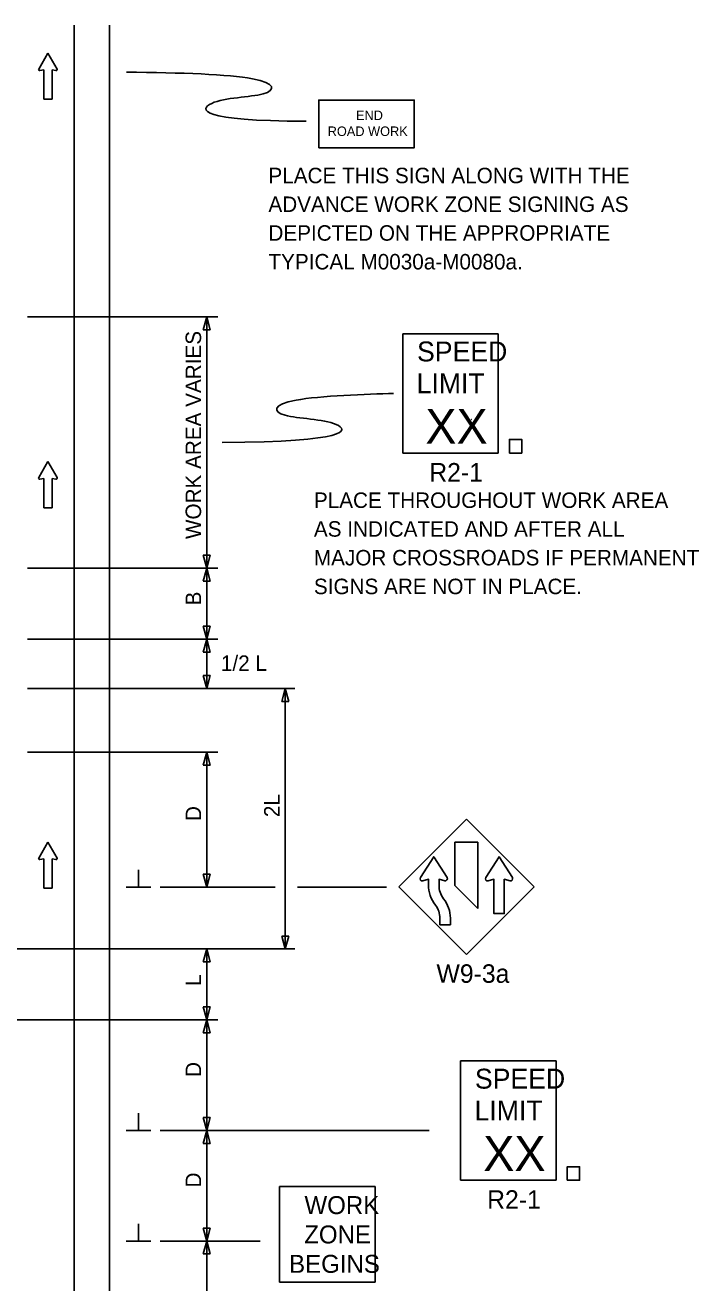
# Model space of a CAD drawing. Extents: x 16737 to 18482, y 6986 to 8195.
# Drawn here: x 17076 to 17381, y 7597 to 8166 of the extents above; entities that cross this region are included whole.
import ezdxf

# ---------------------------------------------------------------- set-up
doc = ezdxf.new("R2010")
doc.units = 0
for name, color, linetype in [('MT_SCRATCH_LEVEL_E', 7, 'Continuous'), ('PAVT_EDGE_EX', 7, 'Continuous'), ('TRAFFIC_SIGNS_PR', 7, 'Continuous'), ('TYPICAL_TEXT_DIMEN_PR', 7, 'Continuous')]:
    doc.layers.add(name, color=color, linetype=linetype)

msp = doc.modelspace()

# ---------------------------------------------------------------- linework, layer by layer
at = {"layer": 'MT_SCRATCH_LEVEL_E'}
for p, q in [((17086.43, 8153.59), (17082.31, 8146.35)), ((17090.57, 8146.35), (17086.43, 8153.59)), ((17082.8, 8145.66), (17084.57, 8145.98)), ((17084.57, 8145.98), (17084.57, 8132.72)), ((17088.32, 8132.72), (17088.32, 8145.98)), ((17088.32, 8145.98), (17090.09, 8145.66)), ((17084.57, 8132.72), (17088.32, 8132.72)), ((17086.43, 7968.78), (17082.32, 7961.54)), ((17086.43, 7968.78), (17082.32, 7961.54)), ((17090.57, 7961.54), (17086.43, 7968.78)), ((17090.57, 7961.54), (17086.43, 7968.78)), ((17082.8, 7960.86), (17084.58, 7961.17)), ((17082.8, 7960.86), (17084.58, 7961.17)), ((17084.58, 7961.17), (17084.58, 7947.91)), ((17084.58, 7961.17), (17084.58, 7947.91)), ((17088.32, 7947.91), (17088.32, 7961.17)), ((17088.32, 7961.17), (17090.09, 7960.86)), ((17088.32, 7947.91), (17088.32, 7961.17)), ((17088.32, 7961.17), (17090.09, 7960.86)), ((17084.58, 7947.91), (17088.32, 7947.91)), ((17084.58, 7947.91), (17088.32, 7947.91)), ((17086.43, 7796.66), (17082.31, 7789.42)), ((17090.57, 7789.42), (17086.43, 7796.66)), ((17082.8, 7788.74), (17084.57, 7789.06)), ((17084.57, 7789.06), (17084.57, 7775.8)), ((17088.32, 7775.8), (17088.32, 7789.06)), ((17088.32, 7789.06), (17090.09, 7788.74)), ((17084.57, 7775.8), (17088.32, 7775.8))]:
    msp.add_line(p, q, dxfattribs=at)
for centre, start, end in [((17082.72, 8146.12), 150.4248, 279.9638), ((17090.16, 8146.12), 260.0362, 29.7731), ((17082.72, 7961.32), 150.4248, 279.9638), ((17082.72, 7961.32), 150.4248, 279.9638), ((17090.16, 7961.32), 260.0362, 29.7731), ((17090.16, 7961.32), 260.0362, 29.7731), ((17082.72, 7789.2), 150.4248, 279.9638), ((17090.16, 7789.2), 260.0362, 29.7731)]:
    msp.add_arc(centre, 0.463, start, end, dxfattribs=at)
at = {"layer": 'PAVT_EDGE_EX'}
for p, q in [((17098.25, 8166.21), (17098.25, 7372.95)), ((17114.25, 8166.21), (17114.25, 7372.95))]:
    msp.add_line(p, q, dxfattribs=at)
at = {"layer": 'TRAFFIC_SIGNS_PR'}
for p, q in [((17246.82, 8026.64), (17290.02, 8026.64)), ((17246.82, 7972.64), (17246.82, 8026.64)), ((17290.02, 7972.64), (17290.02, 8026.64)), ((17246.82, 7972.64), (17290.02, 7972.64)), ((17275.67, 7806.98), (17245.12, 7776.43)), ((17306.21, 7776.43), (17275.67, 7806.98)), ((17270.37, 7796.61), (17270.37, 7777.03)), ((17280.72, 7796.61), (17270.37, 7796.61)), ((17280.72, 7766.67), (17280.72, 7796.61)), ((17270.37, 7777.03), (17280.72, 7766.67)), ((17245.12, 7776.43), (17275.67, 7745.89)), ((17275.67, 7745.89), (17306.21, 7776.43)), ((17272.99, 7697.69), (17316.19, 7697.69)), ((17272.99, 7643.69), (17272.99, 7697.69)), ((17316.19, 7643.69), (17316.19, 7697.69)), ((17191.19, 7597.63), (17191.19, 7640.83)), ((17191.19, 7640.83), (17234.39, 7640.83)), ((17234.39, 7597.63), (17234.39, 7640.83)), ((17272.99, 7643.69), (17316.19, 7643.69)), ((17191.19, 7597.63), (17234.39, 7597.63))]:
    msp.add_line(p, q, dxfattribs=at)
for points in [[(17208.85, 8110.74), (17252.06, 8110.74), (17252.06, 8132.34), (17208.85, 8132.34)], [(17295.03, 7972.64), (17300.63, 7972.64), (17300.63, 7978.81), (17295.03, 7978.81)], [(17321.21, 7643.69), (17326.8, 7643.69), (17326.8, 7649.86), (17321.21, 7649.86)]]:
    msp.add_lwpolyline(points, close=True, dxfattribs=at)
for points in [[(17266.88, 7780.6), (17260.89, 7790.02), (17254.9, 7780.6)], [(17296.39, 7780.6), (17290.4, 7790.02), (17284.4, 7780.6)], [(17255.95, 7779.18), (17258.53, 7779.89), (17258.52, 7777.38)], [(17263.24, 7777.27), (17263.25, 7779.89), (17265.83, 7779.18)], [(17285.45, 7779.18), (17288.04, 7779.89), (17288.04, 7764.37), (17292.76, 7764.37), (17292.76, 7779.89), (17295.34, 7779.18)], [(17263.66, 7762.25), (17263.66, 7759.27), (17268.38, 7759.27), (17268.38, 7762.25)]]:
    msp.add_lwpolyline(points, dxfattribs=at)
for centre, radius, start, end in [((17255.69, 7780.09), 0.945, 147.5204, 285.3986), ((17272.69, 7776.97), 14.17, 178.3293, 218.5427), ((17251.44, 7777.64), 11.81, 358.1894, 0.0048), ((17272.69, 7776.97), 9.45, 178.1936, 218.5465), ((17266.08, 7780.1), 0.947, 254.6828, 32.2708), ((17262.71, 7767.79), 11.81, 74.68, 74.6808), ((17276.85, 7786.94), 11.81, 212.4569, 212.4665), ((17285.2, 7780.09), 0.946, 147.5497, 285.3316), ((17295.59, 7780.09), 0.943, 254.6778, 32.4665), ((17306.35, 7786.94), 11.81, 212.4569, 212.4665), ((17254.21, 7762.25), 9.45, 0, 38.5457), ((17254.21, 7762.25), 14.17, 0, 38.5422)]:
    msp.add_arc(centre, radius, start, end, dxfattribs=at)
at = {"layer": 'TYPICAL_TEXT_DIMEN_PR'}
for p, q in [((17077.19, 8034.26), (17163.25, 8034.26)), ((17156.68, 8028.4), (17158.25, 8034.26)), ((17158.25, 8034.26), (17158.25, 7920.53)), ((17158.25, 8034.26), (17159.82, 8028.4)), ((17158.25, 8028.4), (17156.68, 8028.4)), ((17159.82, 8028.4), (17158.25, 8028.4)), ((17158.25, 7920.53), (17156.68, 7926.4)), ((17156.68, 7926.4), (17158.25, 7926.4)), ((17158.25, 7926.4), (17159.82, 7926.4)), ((17159.82, 7926.4), (17158.25, 7920.53)), ((17077.19, 7920.53), (17163.25, 7920.53)), ((17156.68, 7914.67), (17158.25, 7920.53)), ((17158.25, 7920.53), (17158.25, 7888.46)), ((17158.25, 7920.53), (17159.82, 7914.67)), ((17158.25, 7914.67), (17156.68, 7914.67)), ((17159.82, 7914.67), (17158.25, 7914.67)), ((17158.25, 7888.46), (17156.68, 7894.32)), ((17156.68, 7894.32), (17158.25, 7894.32)), ((17158.25, 7895.55), (17158.25, 7891.96)), ((17158.25, 7894.32), (17159.82, 7894.32)), ((17159.82, 7894.32), (17158.25, 7888.46)), ((17077.19, 7888.46), (17163.25, 7888.46)), ((17156.68, 7882.6), (17158.25, 7888.46)), ((17158.25, 7888.46), (17158.25, 7866.21)), ((17158.25, 7888.46), (17159.82, 7882.6)), ((17158.25, 7882.6), (17156.68, 7882.6)), ((17159.82, 7882.6), (17158.25, 7882.6)), ((17158.25, 7866.21), (17156.68, 7872.07)), ((17156.68, 7872.07), (17158.25, 7872.07)), ((17158.25, 7872.07), (17159.82, 7872.07)), ((17159.82, 7872.07), (17158.25, 7866.21)), ((17077.19, 7866.21), (17198.06, 7866.21)), ((17192.16, 7860.35), (17193.73, 7866.21)), ((17193.73, 7866.21), (17195.3, 7860.35)), ((17193.73, 7866.21), (17193.73, 7748.33)), ((17193.73, 7860.35), (17192.16, 7860.35)), ((17195.3, 7860.35), (17193.73, 7860.35)), ((17077.19, 7837.4), (17163.25, 7837.4)), ((17156.68, 7831.54), (17158.25, 7837.4)), ((17158.25, 7837.4), (17158.25, 7776.36)), ((17158.25, 7837.4), (17159.82, 7831.54)), ((17158.25, 7831.54), (17156.68, 7831.54)), ((17159.82, 7831.54), (17158.25, 7831.54)), ((17127.37, 7776.36), (17127.37, 7784.15)), ((17158.25, 7776.36), (17156.68, 7782.22)), ((17156.68, 7782.22), (17158.25, 7782.22)), ((17158.25, 7782.22), (17159.82, 7782.22)), ((17159.82, 7782.22), (17158.25, 7776.36)), ((17133, 7776.36), (17121.75, 7776.36)), ((17137.25, 7776.36), (17189.24, 7776.36)), ((17199.25, 7776.36), (17239.57, 7776.36)), ((17193.73, 7748.33), (17192.16, 7754.2)), ((17192.16, 7754.2), (17193.73, 7754.2)), ((17193.73, 7754.2), (17195.3, 7754.2)), ((17195.3, 7754.2), (17193.73, 7748.33)), ((17054, 7748.33), (17198.06, 7748.33)), ((17156.68, 7742.47), (17158.25, 7748.33)), ((17158.25, 7748.33), (17158.25, 7716.23)), ((17158.25, 7748.33), (17159.82, 7742.47)), ((17158.25, 7742.47), (17156.68, 7742.47)), ((17159.82, 7742.47), (17158.25, 7742.47)), ((17158.25, 7716.23), (17156.68, 7722.09)), ((17156.68, 7722.09), (17158.25, 7722.09)), ((17158.25, 7722.09), (17159.82, 7722.09)), ((17159.82, 7722.09), (17158.25, 7716.23)), ((17034.65, 7716.23), (17163.25, 7716.23)), ((17156.68, 7710.37), (17158.25, 7716.23)), ((17158.25, 7716.23), (17158.25, 7666.23)), ((17158.25, 7716.23), (17159.82, 7710.37)), ((17158.25, 7710.37), (17156.68, 7710.37)), ((17159.82, 7710.37), (17158.25, 7710.37)), ((17127.37, 7666.23), (17127.37, 7674.02)), ((17158.25, 7666.23), (17156.68, 7672.09)), ((17156.68, 7672.09), (17158.25, 7672.09)), ((17158.25, 7672.09), (17159.82, 7672.09)), ((17159.82, 7672.09), (17158.25, 7666.23)), ((17133, 7666.23), (17121.75, 7666.23)), ((17137.25, 7666.23), (17258.8, 7666.23)), ((17156.68, 7660.37), (17158.25, 7666.23)), ((17158.25, 7666.23), (17158.25, 7616.23)), ((17158.25, 7666.23), (17159.82, 7660.37)), ((17158.25, 7660.37), (17156.68, 7660.37)), ((17159.82, 7660.37), (17158.25, 7660.37)), ((17127.37, 7616.23), (17127.37, 7624.02)), ((17158.25, 7616.23), (17156.68, 7622.09)), ((17156.68, 7622.09), (17158.25, 7622.09)), ((17158.25, 7622.09), (17159.82, 7622.09)), ((17159.82, 7622.09), (17158.25, 7616.23)), ((17133, 7616.23), (17121.75, 7616.23)), ((17137.25, 7616.23), (17182.4, 7616.23)), ((17156.68, 7610.37), (17158.25, 7616.23)), ((17158.25, 7616.23), (17159.82, 7610.37)), ((17158.25, 7616.23), (17158.25, 7566.23)), ((17158.25, 7610.37), (17156.68, 7610.37)), ((17159.82, 7610.37), (17158.25, 7610.37))]:
    msp.add_line(p, q, dxfattribs=at)
for points, degree in [([(17203.12, 8122.78), (17154.66, 8122.78), (17154.66, 8133.54), (17189.57, 8133.54), (17189.57, 8143.2), (17146.71, 8144.72), (17121.92, 8144.98)], 3), ([(17165.27, 7977.42), (17222.82, 7977.8), (17222.39, 7988.15), (17187.91, 7988.15), (17187.91, 7997.81), (17230.77, 7999.33), (17242.68, 7999.59)], 3), ([(17277.82, 7987.86), (17277.84, 7987.86), (17277.85, 7987.86), (17277.85, 7987.86)], 2)]:
    msp.add_open_spline(points, degree=degree, dxfattribs=at)

# ---------------------------------------------------------------- texts
at = {"layer": 'TRAFFIC_SIGNS_PR'}
for s, height, p in [('END', 4.31, (17225.73, 8123.26)), ('ROAD WORK', 4.31, (17212.92, 8116.07)), ('PLACE THIS SIGN ALONG WITH THE', 7, (17186.12, 8094.71)), ('ADVANCE WORK ZONE SIGNING AS', 7, (17186.12, 8081.71)), ('DEPICTED ON THE APPROPRIATE', 7, (17186.12, 8068.71)), ('TYPICAL M0030a-M0080a.', 7, (17186.12, 8055.71)), ('SPEED', 9, (17253.31, 8014.11)), ('LIMIT', 9, (17253.12, 7999.71)), ('XX', 15.785, (17257.07, 7976.86)), ('R2-1', 8.37, (17258.83, 7959.77)), ('PLACE THROUGHOUT WORK AREA', 7, (17206.68, 7947.83)), ('AS INDICATED AND AFTER ALL', 7, (17206.68, 7934.83)), ('MAJOR CROSSROADS IF PERMANENT', 7, (17206.68, 7921.83)), ('SIGNS ARE NOT IN PLACE.', 7, (17206.68, 7908.83)), ('W9-3a', 8.37, (17262.1, 7733.02)), ('SPEED', 9, (17279.48, 7685.16)), ('LIMIT', 9, (17279.3, 7670.76)), ('XX', 15.785, (17283.24, 7647.92)), ('WORK', 8.119, (17202.44, 7628.41)), ('R2-1', 8.37, (17285, 7630.82)), ('ZONE', 8.119, (17202.31, 7615.13)), ('BEGINS', 8.119, (17195.48, 7601.84))]:
    msp.add_text(s, height=height, dxfattribs=at).set_placement(p)
at = {"layer": 'TYPICAL_TEXT_DIMEN_PR'}
for s, p in [('WORK AREA VARIES', (17155.69, 7933.75)), ('B', (17155.69, 7903.73)), ('2L', (17191.17, 7807.99)), ('D', (17155.69, 7806.21)), ('L', (17155.69, 7731.64)), ('D', (17155.69, 7690.45)), ('D', (17155.69, 7640.45))]:
    msp.add_text(s, height=7, rotation=90, dxfattribs=at).set_placement(p)
msp.add_text('1/2 L', height=7, dxfattribs=at).set_placement((17164.65, 7874.13))

doc.saveas('drawing.dxf')
